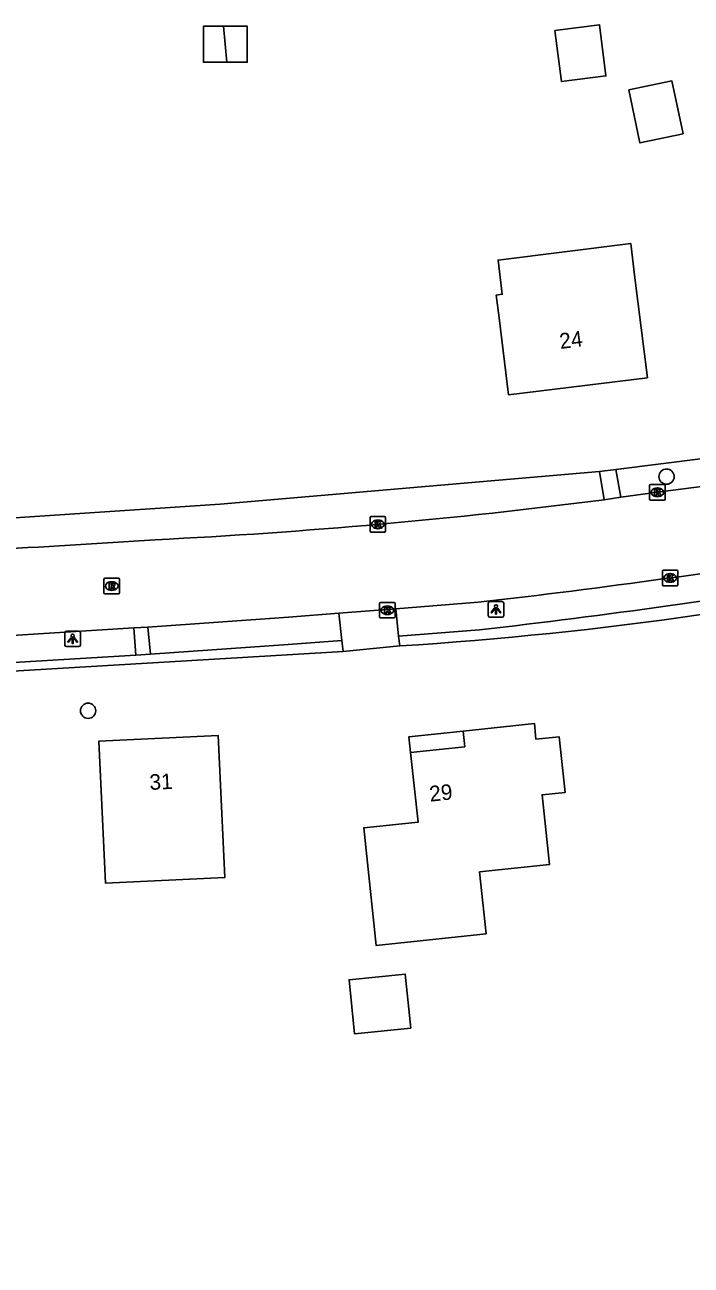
# Model space of a CAD drawing. Extents: x 162675 to 163482, y 379761 to 381227.
# Drawn here: x 163145.1 to 163187.9, y 380672.3 to 380752 of the extents above; entities that cross this region are included whole.
import ezdxf

# ---------------------------------------------------------------- set-up
doc = ezdxf.new("R2010")
doc.units = 0
for name, color, linetype in [('IMGEO_Boom', 7, 'Continuous'), ('IMGEO_Groenvoorziening', 7, 'Continuous'), ('IMGEO_Haag', 7, 'Continuous'), ('IMGEO_Kolk', 7, 'Continuous'), ('IMGEO_Lichtpunt', 7, 'Continuous'), ('IMGEO_Pand', 7, 'Continuous'), ('IMGEO_Pand_nummerreeks', 7, 'Continuous'), ('IMGEO_Pand_overbouw', 7, 'Continuous'), ('IMGEO_Parkeervlak_halfverhard', 7, 'Continuous'), ('IMGEO_Rijbaan_lokaal_gesloten', 7, 'Continuous'), ('IMGEO_Rioolput', 7, 'Continuous'), ('IMGEO_Voetpad_open', 7, 'Continuous')]:
    doc.layers.add(name, color=color, linetype=linetype)

msp = doc.modelspace()

# ---------------------------------------------------------------- linework, layer by layer
at = {"layer": 'IMGEO_Boom'}
for centre in [(163186.318, 380722.962), (163149.161, 380707.918)]:
    msp.add_circle(centre, 0.489, dxfattribs=at)
at = {"layer": 'IMGEO_Groenvoorziening'}
for points in [[(163183.053, 380723.421), (163188.671, 380724.124)], [(163131.621, 380719.387), (163135.984, 380719.633), (163137.35, 380719.841), (163157.635, 380721.186), (163182.017, 380723.287)], [(163165.538, 380711.722), (163118.769, 380708.949), (163114.577, 380708.178), (163114.12, 380705.969), (163115.857, 380683.956), (163117.643, 380664.6), (163117.707, 380663.313)]]:
    msp.add_lwpolyline(points, dxfattribs=at)
at = {"layer": 'IMGEO_Haag'}
msp.add_arc((163153.661, 380955.763), 244.174, 273.64273, 282.71441, dxfattribs=at)
at = {"layer": 'IMGEO_Kolk'}
for p, q in [((163185.301, 380722.458), (163186.153, 380722.458)), ((163185.226, 380721.532), (163185.226, 380722.384)), ((163185.737, 380721.678), (163185.712, 380721.678)), ((163185.714, 380722.238), (163185.739, 380722.238)), ((163186.227, 380722.384), (163186.227, 380721.532)), ((163186.153, 380721.458), (163185.301, 380721.458)), ((163167.271, 380719.469), (163167.271, 380720.321)), ((163167.346, 380720.395), (163168.198, 380720.395)), ((163167.759, 380720.175), (163167.784, 380720.175)), ((163168.272, 380720.321), (163168.272, 380719.469)), ((163168.198, 380719.395), (163167.346, 380719.395)), ((163167.782, 380719.615), (163167.757, 380719.615)), ((163186.045, 380716.025), (163186.045, 380716.877)), ((163186.12, 380716.951), (163186.972, 380716.951)), ((163187.046, 380716.877), (163187.046, 380716.025)), ((163186.556, 380716.171), (163186.531, 380716.171)), ((163186.533, 380716.731), (163186.558, 380716.731)), ((163186.972, 380715.951), (163186.12, 380715.951)), ((163167.881, 380713.952), (163167.881, 380714.804)), ((163167.956, 380714.878), (163168.808, 380714.878)), ((163168.369, 380714.658), (163168.394, 380714.658)), ((163168.882, 380714.804), (163168.882, 380713.952)), ((163168.808, 380713.878), (163167.956, 380713.878)), ((163168.392, 380714.098), (163168.367, 380714.098))]:
    msp.add_line(p, q, dxfattribs=at)
for points in [[(163185.301, 380722.458), (163186.153, 380722.458)], [(163185.226, 380721.532), (163185.226, 380722.384)], [(163185.547, 380722.158), (163185.67, 380722.158), (163185.67, 380722.007), (163185.8, 380722.158), (163185.964, 380722.158), (163185.818, 380722.007), (163185.971, 380721.758), (163185.819, 380721.758), (163185.734, 380721.922), (163185.67, 380721.855), (163185.67, 380721.758), (163185.547, 380721.758), (163185.547, 380722.158)], [(163186.227, 380722.384), (163186.227, 380721.532)], [(163186.153, 380721.458), (163185.301, 380721.458)], [(163167.271, 380719.469), (163167.271, 380720.321)], [(163167.346, 380720.395), (163168.198, 380720.395)], [(163167.592, 380720.095), (163167.715, 380720.095), (163167.715, 380719.944), (163167.845, 380720.095), (163168.009, 380720.095), (163167.863, 380719.944), (163168.016, 380719.695), (163167.864, 380719.695), (163167.779, 380719.859), (163167.715, 380719.792), (163167.715, 380719.695), (163167.592, 380719.695), (163167.592, 380720.095)], [(163168.272, 380720.321), (163168.272, 380719.469)], [(163168.198, 380719.395), (163167.346, 380719.395)], [(163186.045, 380716.025), (163186.045, 380716.877)], [(163186.12, 380716.951), (163186.972, 380716.951)], [(163187.046, 380716.877), (163187.046, 380716.025)], [(163186.366, 380716.651), (163186.489, 380716.651), (163186.489, 380716.5), (163186.619, 380716.651), (163186.783, 380716.651), (163186.637, 380716.5), (163186.79, 380716.251), (163186.638, 380716.251), (163186.553, 380716.415), (163186.489, 380716.348), (163186.489, 380716.251), (163186.366, 380716.251), (163186.366, 380716.651)], [(163186.972, 380715.951), (163186.12, 380715.951)], [(163167.881, 380713.952), (163167.881, 380714.804)], [(163167.956, 380714.878), (163168.808, 380714.878)], [(163168.202, 380714.578), (163168.325, 380714.578), (163168.325, 380714.427), (163168.455, 380714.578), (163168.619, 380714.578), (163168.473, 380714.427), (163168.626, 380714.178), (163168.474, 380714.178), (163168.389, 380714.342), (163168.325, 380714.275), (163168.325, 380714.178), (163168.202, 380714.178), (163168.202, 380714.578)], [(163168.882, 380714.804), (163168.882, 380713.952)], [(163168.808, 380713.878), (163167.956, 380713.878)]]:
    msp.add_lwpolyline(points, dxfattribs=at)
for centre, start, end in [((163185.303, 380722.382), 91.55205, 178.44795), ((163185.303, 380722.382), 91.55205, 178.44795), ((163186.151, 380722.382), 1.55205, 88.44795), ((163186.151, 380722.382), 1.55205, 88.44795), ((163185.303, 380721.534), 181.55205, 268.44795), ((163185.303, 380721.534), 181.55205, 268.44795), ((163186.151, 380721.534), 271.55205, 358.44795), ((163186.151, 380721.534), 271.55205, 358.44795), ((163167.348, 380720.319), 91.55205, 178.44795), ((163167.348, 380720.319), 91.55205, 178.44795), ((163168.196, 380720.319), 1.55205, 88.44795), ((163168.196, 380720.319), 1.55205, 88.44795), ((163167.348, 380719.471), 181.55205, 268.44795), ((163167.348, 380719.471), 181.55205, 268.44795), ((163168.196, 380719.471), 271.55205, 358.44795), ((163168.196, 380719.471), 271.55205, 358.44795), ((163186.122, 380716.875), 91.55205, 178.44795), ((163186.122, 380716.875), 91.55205, 178.44795), ((163186.97, 380716.875), 1.55205, 88.44795), ((163186.97, 380716.875), 1.55205, 88.44795), ((163186.122, 380716.027), 181.55205, 268.44795), ((163186.122, 380716.027), 181.55205, 268.44795), ((163186.97, 380716.027), 271.55205, 358.44795), ((163186.97, 380716.027), 271.55205, 358.44795), ((163167.958, 380714.802), 91.55205, 178.44795), ((163167.958, 380714.802), 91.55205, 178.44795), ((163168.806, 380714.802), 1.55205, 88.44795), ((163168.806, 380714.802), 1.55205, 88.44795), ((163167.958, 380713.954), 181.55205, 268.44795), ((163167.958, 380713.954), 181.55205, 268.44795), ((163168.806, 380713.954), 271.55205, 358.44795), ((163168.806, 380713.954), 271.55205, 358.44795)]:
    msp.add_arc(centre, 0.0765, start, end, dxfattribs=at)
for centre, major_axis, ratio, start_param, end_param in [((163185.713, 380721.958), (-0.387, 0.002), 0.722429, 4.712389, 7.853982), ((163185.738, 380721.958), (-0.39, 0.002), 0.717154, 1.570796, 4.712389), ((163167.758, 380719.895), (-0.387, 0.002), 0.722429, 4.712389, 7.853982), ((163167.783, 380719.895), (-0.39, 0.002), 0.717154, 1.570796, 4.712389), ((163186.532, 380716.451), (-0.387, 0.002), 0.722429, 4.712389, 7.853982), ((163186.557, 380716.451), (-0.39, 0.002), 0.717154, 1.570796, 4.712389), ((163168.368, 380714.378), (-0.387, 0.002), 0.722429, 4.712389, 7.853982), ((163168.393, 380714.378), (-0.39, 0.002), 0.717154, 1.570796, 4.712389)]:
    msp.add_ellipse(centre, major_axis=major_axis, ratio=ratio, start_param=start_param, end_param=end_param, dxfattribs=at)
at = {"layer": 'IMGEO_Lichtpunt'}
for p, q in [((163174.862, 380714.835), (163174.862, 380714.028)), ((163174.862, 380714.835), (163174.862, 380714.028)), ((163175.764, 380714.93), (163174.956, 380714.93)), ((163175.764, 380714.93), (163174.956, 380714.93)), ((163175.858, 380714.028), (163175.858, 380714.835)), ((163175.858, 380714.028), (163175.858, 380714.835)), ((163174.956, 380713.934), (163175.764, 380713.934)), ((163174.956, 380713.934), (163175.764, 380713.934)), ((163147.67, 380712.943), (163147.67, 380712.136)), ((163147.67, 380712.943), (163147.67, 380712.136)), ((163148.572, 380713.038), (163147.764, 380713.038)), ((163148.572, 380713.038), (163147.764, 380713.038)), ((163148.666, 380712.136), (163148.666, 380712.943)), ((163148.666, 380712.136), (163148.666, 380712.943)), ((163147.764, 380712.042), (163148.572, 380712.042)), ((163147.764, 380712.042), (163148.572, 380712.042))]:
    msp.add_line(p, q, dxfattribs=at)
for points in [[(163175.236, 380714.499), (163175.275, 380714.471), (163175.087, 380714.209), (163175.049, 380714.236), (163175.236, 380714.499)], [(163175.448, 380714.471), (163175.486, 380714.498), (163175.673, 380714.236), (163175.634, 380714.208), (163175.448, 380714.471)], [(163175.338, 380714.451), (163175.385, 380714.451), (163175.385, 380714.129), (163175.338, 380714.129), (163175.338, 380714.451)], [(163148.044, 380712.607), (163148.083, 380712.579), (163147.895, 380712.317), (163147.857, 380712.344), (163148.044, 380712.607)], [(163148.146, 380712.559), (163148.193, 380712.559), (163148.193, 380712.237), (163148.146, 380712.237), (163148.146, 380712.559)], [(163148.256, 380712.579), (163148.294, 380712.606), (163148.481, 380712.344), (163148.442, 380712.316), (163148.256, 380712.579)]]:
    msp.add_lwpolyline(points, dxfattribs=at)
for centre in [(163175.361, 380714.633), (163148.169, 380712.741)]:
    msp.add_circle(centre, 0.0994, dxfattribs=at)
for centre, start, end in [((163174.956, 380714.835), 90, 180), ((163174.956, 380714.835), 90, 180), ((163175.764, 380714.835), 0, 90), ((163175.764, 380714.835), 0, 90), ((163174.956, 380714.028), 180, 270), ((163174.956, 380714.028), 180, 270), ((163175.764, 380714.028), 270, 0), ((163175.764, 380714.028), 270, 360), ((163147.764, 380712.943), 90, 180), ((163147.764, 380712.943), 90, 180), ((163148.572, 380712.943), 0, 90), ((163148.572, 380712.943), 0, 90), ((163147.764, 380712.136), 180, 270), ((163147.764, 380712.136), 180, 270), ((163148.572, 380712.136), 270, 0), ((163148.572, 380712.136), 270, 360)]:
    msp.add_arc(centre, 0.0946, start, end, dxfattribs=at)
at = {"layer": 'IMGEO_Pand'}
for points in [[(163179.147, 380751.64), (163179.557, 380748.351), (163182.42, 380748.708), (163182.01, 380751.997), (163179.147, 380751.64)], [(163158.064, 380749.588), (163156.572, 380749.588), (163156.572, 380751.909), (163157.848, 380751.909)], [(163157.848, 380751.909), (163159.381, 380751.909), (163159.381, 380749.588), (163158.064, 380749.588)], [(163158.064, 380749.588), (163157.848, 380751.909)], [(163183.889, 380747.81), (163184.606, 380744.41), (163187.376, 380744.994), (163186.659, 380748.394), (163183.889, 380747.81)], [(163185.088, 380729.32), (163176.172, 380728.21), (163175.554, 380733.172), (163175.372, 380734.632), (163175.765, 380734.681), (163175.492, 380736.873), (163184.014, 380737.935), (163184.287, 380735.743), (163185.088, 380729.32)], [(163174.305, 380697.56), (163174.723, 380693.581), (163167.661, 380692.84), (163166.868, 380700.398), (163170.354, 380700.766), (163169.871, 380705.238), (163173.352, 380705.602), (163173.246, 380706.596), (163177.838, 380707.095), (163177.923, 380706.085), (163179.416, 380706.245), (163179.8, 380702.671), (163178.32, 380702.516), (163178.791, 380698.03), (163174.305, 380697.56)], [(163157.755, 380701.323), (163157.947, 380697.204), (163150.274, 380696.846), (163150.083, 380700.958), (163149.85, 380705.96), (163157.522, 380706.317), (163157.755, 380701.323)], [(163169.882, 380687.521), (163166.28, 380687.153), (163165.925, 380690.627), (163169.526, 380690.996), (163169.882, 380687.521)]]:
    msp.add_lwpolyline(points, dxfattribs=at)
at = {"layer": 'IMGEO_Pand_overbouw'}
msp.add_lwpolyline([(163169.871, 380705.238), (163173.352, 380705.602), (163173.246, 380706.596), (163169.759, 380706.237)], close=True, dxfattribs=at)
at = {"layer": 'IMGEO_Parkeervlak_halfverhard'}
for points in [[(163174.31, 380713.111), (163169.108, 380712.716)], [(163165.457, 380712.44), (163162.021, 380712.179), (163153.17, 380711.561)], [(163152.219, 380711.484), (163142.245, 380710.899), (163120.382, 380709.791)]]:
    msp.add_lwpolyline(points, dxfattribs=at)
msp.add_arc((163116.373, 381213.905), 504.134, 276.59921, 279.37128, dxfattribs=at)
at = {"layer": 'IMGEO_Rijbaan_lokaal_gesloten'}
for points in [[(163188.891, 380722.38), (163185.727, 380721.958), (163183.388, 380721.635)], [(163183.388, 380721.635), (163182.318, 380721.48)], [(163168.921, 380714.47), (163174.22, 380714.886)], [(163153.006, 380713.282), (163162.041, 380713.929), (163165.261, 380714.182)], [(163165.261, 380714.182), (163168.921, 380714.47)], [(163120.324, 380711.563), (163142.232, 380712.632), (163152.095, 380713.243)], [(163152.095, 380713.243), (163153.006, 380713.282)]]:
    msp.add_lwpolyline(points, dxfattribs=at)
for centre, radius, start, end in [((163135.125, 381087.021), 368.575, 272.85295, 277.35645), ((163094.024, 381620.626), 903.681, 272.385816, 273.77174), ((163119.092, 381198.326), 486.573, 276.50553, 279.3548)]:
    msp.add_arc(centre, radius, start, end, dxfattribs=at)
at = {"layer": 'IMGEO_Rioolput'}
for p, q in [((163150.18, 380715.503), (163150.18, 380716.355)), ((163150.255, 380716.429), (163151.107, 380716.429)), ((163150.668, 380716.209), (163150.693, 380716.209)), ((163151.181, 380716.355), (163151.181, 380715.503)), ((163151.107, 380715.429), (163150.255, 380715.429)), ((163150.691, 380715.649), (163150.666, 380715.649))]:
    msp.add_line(p, q, dxfattribs=at)
for points in [[(163150.18, 380715.503), (163150.18, 380716.355)], [(163150.255, 380716.429), (163151.107, 380716.429)], [(163150.769, 380716.127), (163150.517, 380716.129), (163150.517, 380715.729)], [(163151.181, 380716.355), (163151.181, 380715.503)], [(163151.107, 380715.429), (163150.255, 380715.429)], [(163150.517, 380715.729), (163150.641, 380715.729), (163150.641, 380715.891), (163150.652, 380715.891)], [(163150.695, 380716.048), (163150.641, 380716.048), (163150.641, 380715.967)], [(163150.641, 380715.967), (163150.693, 380715.967)], [(163150.699, 380715.862), (163150.77, 380715.729), (163150.91, 380715.729), (163150.845, 380715.855)]]:
    msp.add_lwpolyline(points, dxfattribs=at)
for centre, radius, start, end in [((163150.257, 380716.353), 0.0765, 91.55205, 178.44795), ((163150.257, 380716.353), 0.0765, 91.55205, 178.44795), ((163150.768, 380716.017), 0.109, 350.36119, 89.41601), ((163151.105, 380716.353), 0.0765, 1.55205, 88.44795), ((163151.105, 380716.353), 0.0765, 1.55205, 88.44795), ((163150.257, 380715.505), 0.0765, 181.55205, 268.44795), ((163150.257, 380715.505), 0.0765, 181.55205, 268.44795), ((163150.651, 380715.838), 0.0533, 26.02933, 88.69889), ((163150.677, 380716.156), 0.19, 274.7715, 282.96867), ((163150.701, 380715.952), 0.0964, 77.00612, 93.18647), ((163150.715, 380716.009), 0.0378, 276.66336, 79.67722), ((163150.766, 380716.017), 0.112, 277.58423, 350.98172), ((163150.75, 380715.802), 0.108, 29.51342, 73.79051), ((163151.105, 380715.505), 0.0765, 271.55205, 358.44795), ((163151.105, 380715.505), 0.0765, 271.55205, 358.44795)]:
    msp.add_arc(centre, radius, start, end, dxfattribs=at)
for centre, major_axis, ratio, start_param, end_param in [((163150.667, 380715.929), (-0.387, 0.002), 0.722429, 4.712389, 7.853982), ((163150.692, 380715.929), (-0.39, 0.002), 0.717154, 1.570796, 4.712389)]:
    msp.add_ellipse(centre, major_axis=major_axis, ratio=ratio, start_param=start_param, end_param=end_param, dxfattribs=at)
at = {"layer": 'IMGEO_Voetpad_open'}
for points in [[(163182.017, 380723.287), (163183.053, 380723.421)], [(163182.318, 380721.48), (163182.017, 380723.287)], [(163183.388, 380721.635), (163183.053, 380723.421)], [(163165.261, 380714.182), (163165.457, 380712.44)], [(163169.108, 380712.716), (163168.921, 380714.47)], [(163152.095, 380713.243), (163152.219, 380711.484)], [(163153.17, 380711.561), (163153.006, 380713.282)], [(163165.538, 380711.722), (163165.457, 380712.44)], [(163169.175, 380712.083), (163165.538, 380711.722)], [(163169.108, 380712.716), (163169.175, 380712.083)], [(163153.17, 380711.561), (163152.219, 380711.484)]]:
    msp.add_lwpolyline(points, dxfattribs=at)

# ---------------------------------------------------------------- texts
at = {"layer": 'IMGEO_Pand_nummerreeks'}
for s, rotation, p in [('24', 7.09895, (163179.499, 380731.164)), ('31', 2.66421, (163153.126, 380702.829)), ('29', 5.96592, (163171.13, 380702.072))]:
    msp.add_text(s, height=1, rotation=rotation, dxfattribs=at).set_placement(p)

doc.saveas('drawing.dxf')
